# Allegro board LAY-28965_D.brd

Outline 66.22 x 66.22 mm; copper layers: TOP, L2, L3, BOTTOM. Coordinates in mm from the lower left corner of the outline.
Outline path: 0,66.22 66.22,66.22 66.22,0 0,0 0,66.22

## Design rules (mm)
constraint set DEFAULT: min track width 0.2, pair gap 0.2

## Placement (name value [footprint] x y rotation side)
C1  0.47UF  [CC0603_OV]  56.88 27.21 270 bottom
C5  100PF  [CC0603_OV]  42.8 57.2 90 bottom
C6  100PF  [CC0603_OV]  61.33 53.51 270 bottom
C7  0.01uF  [CC0402_25]  56 43.9 180 bottom
C8  0.01uF  [CC0402_25]  57 46.99 180 bottom
C9  0.01uF  [CC0402_25]  60.02 48.39 180 bottom
C10  0.01uF  [CC0402_25]  56.08 36.63 180 bottom
C11  0.01uF  [CC0402_25]  60.02 36.2 0 bottom
C12  0.01uF  [CC0402_25]  60.02 33.43 180 bottom
C13  2200pF  [CC0402_25]  6.67 47.16 270 bottom
C14  15nF  [CC0402_25]  10.38 49.01 0 bottom
C15  470PF  [CC0603_OV]  3.09 47.1 0 bottom
C16  220PF  [CC0603_OV]  33.27 57.2 90 bottom
C17  2200pF  [CC0402_25]  5.73 59.29 180 bottom
C18  15nF  [CC0402_25]  10.81 59.29 0 bottom
C20  0.1uF  [CC0603_OV]  51.79 32.77 90 bottom
C21  2200pF  [CC0402_25]  35.05 56.94 270 bottom
D1  MMBZ27VCLT1  [SOT23_A]  27.44 58.28 180 bottom
D2  MMBZ27VCLT1  [SOT23_A]  21.73 58.65 180 bottom
D3  MMBZ27VCLT1  [SOT23_A]  54.63 58.11 180 bottom
D4  MMBZ27VCLT1  [SOT23_A]  50.68 57.99 90 bottom
D5  MMBZ27VCLT1  [SOT23_A]  60.39 58.11 180 bottom
J1  HDR 1X2  [HDR102]  54.33 26.93 270 top
J2  NP583-016-009  [SKT_QFN16_0P8_25SQ_TH]  34.1 35.75 0 top
J3  HDR 1X2  [HDR102]  51.79 23.88 90 top
J4  HDR 1X2  [HDR102]  55.73 19.05 0 top
J5  HDR 1X2  [HDR102]  52.68 19.05 0 top
J6  HDR 1X2  [HDR102]  49.63 19.05 0 top
J7  HDR 1X2  [HDR102]  13.57 22.28 180 top
J8  HDR 1X2  [HDR102]  16.74 22.28 180 top
J9  CON 2 SKT  [CON_2P_1MM_SM_4P2X3P3]  17.41 52.94 180 top
J10  CON 2 SKT  [CON_2P_1MM_SM_4P2X3P3]  28.93 52.94 180 top
J11  CON 2 SKT  [CON_2P_1MM_SM_4P2X3P3]  56.07 52.94 180 top
J12  CON 2 SKT  [CON_2P_1MM_SM_4P2X3P3]  50.31 52.94 180 top
J13  CON 2 SKT  [CON_2P_1MM_SM_4P2X3P3]  61.83 52.94 180 top
J14  HDR 1X2  [HDR102]  45.97 51.99 180 top
J16  CON 8 SKT  [CON_8P_1MM_SM_10P2X3P3]  22.46 16.27 180 top
J17  CON 8 SKT  [CON_8P_1MM_SM_10P2X3P3]  12.68 35.69 270 top
J19  CON 8 SKT  [CON_8P_1MM_SM_10P2X3P3]  54.51 40.52 90 top
J28  HDR 1X3  [HDR103_A]  32.97 47.04 270 top
J30  HDR 1X3  [HDR103_A]  47.75 31.41 0 top
J33  HDR 1X3  [HDR103_A]  9.87 51.99 180 top
J34  HDR 1X2  [HDR102]  3.5 51.99 180 top
J36  HDR 1X2  [HDR102]  39.62 51.99 180 top
J37  HDR 1X3  [HDR103_A]  42.24 47.04 270 top
J42  HDR 1X3  [HDR103_A]  6.67 51.99 180 top
J45  CON 2 SKT  [CON_2P_1MM_SM_4P2X3P3]  23.17 52.94 180 top
J46  HDR 1X3  [HDR103_A]  56.87 30.1 270 top
J47  HDR 1X3  [HDR103_A]  47.75 40.3 0 top
J48  5103310-3  [HDR_16M_100_TH_RA]  29.31 12.58 270 top
J49  HDR 1X3  [HDR103_A]  13.07 51.99 180 top
J50  HDR 1X2  [HDR102]  33.27 51.99 180 top
J51  HDR 1X2  [HDR102]  42.8 51.99 180 top
J52  HDR 1X2  [HDR102]  36.45 51.99 180 top
J53  CON 2 SKT  [CON_2P_1MM_SM_4P2X3P3]  62.84 24.39 270 top
J54  5103310-1  [HDR_10M_100_TH_RA]  54.08 12.58 270 top
J55  HDR 1X3  [HDR103_A]  23.73 47.04 270 top
JP3  TEST_POINT  [TP_TH_063]  61.19 30.1 0 top
JP4  5124  [TP_TH_063]  44.68 16.64 0 top
JP5  5124  [TP_TH_063]  37.06 16.64 0 top
JP6  5124  [TP_TH_063]  40.87 16.64 0 top
JP9  5124  [TP_TH_063]  33.25 16.64 0 top
JP11  TEST POINT  [TP_TH_063]  7.99 62.14 0 top
JP12  TESTPOINT GREEN  [TP_TH_063]  39.62 60.56 0 top
JP13  TESTPOINT GREEN  [TP_TH_063]  43.43 60.56 0 top
JP14  TESTPOINT GREEN  [TP_TH_063]  58.11 60.56 0 top
JP15  5007  [TP_TH_063]  47.24 60.56 0 top
JP16  5007  [TP_TH_063]  62.51 38.61 0 top
JP17  5124  [TP_TH_063]  62.51 34.8 0 top
JP18  5007  [TP_TH_063]  62.51 42.8 0 top
JP19  5124  [TP_TH_063]  62.51 46.99 0 top
JP20  TEST POINT BLUE  [TP_TH_063]  16.12 62.14 0 top
JP21  5007  [TP_TH_063]  5.44 41.91 0 top
JP22  5007  [TP_TH_063]  5.44 37.59 0 top
JP23  5007  [TP_TH_063]  5.44 33.27 0 top
JP25  5006  [TP_TH_063]  12.06 62.14 0 top
JP26  5007  [TP_TH_063]  5.44 29.46 0 top
JP27  5006  [TP_TH_063]  50.08 43.99 0 top
JP28  5006  [TP_TH_063]  8.31 18.05 0 top
JP29  5006  [TP_TH_063]  15.13 46.7 0 top
JP30  5006  [TP_TH_063]  63.37 10.12 0 top
JP31  TEST_POINT  [TP_TH_063]  46.91 47.23 0 top
JP32  TESTPOINT GREEN  [TP_TH_063]  59.45 19.4 0 top
JP33  TESTPOINT GREEN  [TP_TH_063]  63 15.77 0 top
JP34  TEST POINT BLUE  [TP_TH_063]  52.82 60.57 0 top
MH1  MH_100mil  [C100-100N]  2.54 63.68 0 top
MH2  MH_100mil  [C100-100N]  2.9 2.67 0 top
MH3  MH_100mil  [C100-100N]  63.68 63.68 0 top
MH4  MH_100mil  [C100-100N]  63.68 2.54 0 top
NOREF  -  []  7.03 37.59 0 top
NOREF#2  -  [unnamed#2]  63.36 60.1 0 top
NOREF#3  -  []  64.1 42.8 0 top
NOREF#4  -  []  48.5 47.23 0 top
NOREF#5  -  []  54.41 60.57 0 top
NOREF#6  -  []  32.61 -3.38 0 top
NOREF#7  -  []  43.92 10.04 90 top
NOREF#8  -  []  7.03 41.91 0 top
NOREF#9  -  []  23.9 23.4 90 top
NOREF#10  -  []  21.29 60.05 0 top
NOREF#11  -  []  22.3 21.8 0 top
NOREF#12  -  []  38.65 16.64 0 top
NOREF#13  -  []  9.58 62.14 0 top
NOREF#14  -  []  2.5 6.26 90 top
NOREF#15  -  []  32.61 -3.38 0 top
NOREF#16  -  []  48.83 60.56 0 top
NOREF#17  -  []  41.21 60.56 0 top
NOREF#18  -  []  -380.1 233.02 0 top
NOREF#19  -  []  13.64 62.14 0 top
NOREF#20  -  []  42.59 -3.38 90 top
NOREF#21  -  []  7.03 33.27 0 top
NOREF#22  -  []  64.1 38.61 0 top
NOREF#23  -  []  20.25 19.75 0 top
NOREF#24  -  [unnamed#2]  63.48 6.35 0 top
NOREF#25  -  []  51.54 12.58 0 top
NOREF#26  -  []  -443.6 -259.85 0 top
NOREF#27  -  []  51.67 43.99 0 top
NOREF#28  -  []  64.95 10.12 0 top
NOREF#29  -  []  2.9 2.67 0 top
NOREF#30  -  []  0 66.22 0 top
NOREF#31  -  []  22.3 21.8 90 top
NOREF#32  -  []  61.04 19.4 0 top
NOREF#33  -  []  21.45 23.1 90 top
NOREF#34  -  []  30.55 32 0 top
NOREF#35  -  []  2.9 2.67 0 top
NOREF#36  -  []  -240.18 -122.17 0 top
NOREF#37  -  []  2.9 2.67 0 top
NOREF#38  -  []  64.59 15.77 0 top
NOREF#39  -  []  27.77 -77.15 0 top
NOREF#40  -  []  0 0 90 top
NOREF#41  -  []  34.27 35.69 0 top
NOREF#42  -  []  7.03 29.46 0 top
NOREF#43  -  []  36.25 31.2 90 top
NOREF#44  -  []  29.55 32.4 0 top
NOREF#45  -  []  64.1 46.99 0 top
NOREF#46  -  []  43.92 12.58 0 top
NOREF#47  -  []  45.02 60.56 0 top
NOREF#48  -  []  17.71 62.14 0 top
NOREF#49  -  []  59.7 60.56 0 top
NOREF#50  -  []  0 0 0 top
NOREF#51  -  []  62.78 30.1 0 top
NOREF#52  -  []  28.55 32.8 0 top
NOREF#53  -  [unnamed#2]  2.81 59.9 0 top
NOREF#54  -  []  21.45 28.6 90 top
NOREF#55  -  []  46.27 16.64 0 top
NOREF#56  -  []  35.25 32.8 90 top
NOREF#57  -  []  1.28 9.91 0 top
NOREF#58  -  []  64.1 34.8 0 top
NOREF#59  -  []  -17.22 -67.1 0 top
NOREF#60  -  []  42.46 16.64 0 top
NOREF#61  -  []  0 0 0 top
NOREF#62  -  []  2.9 2.67 90 top
NOREF#63  -  []  16.72 46.7 0 top
NOREF#64  -  []  34.84 16.64 0 top
NOREF#65  -  []  9.9 18.05 0 top
NOREF#66  -  []  2.9 2.67 0 top
NOREF#67  -  [unnamed#2]  63.48 6.35 180 bottom
NOREF#68  -  []  44.64 25.47 180 bottom
NOREF#69  -  []  59.81 1.22 180 bottom
NOREF#70  -  [unnamed#2]  63.36 60.1 180 bottom
NOREF#71  -  []  12.45 26.16 90 bottom
NOREF#72  -  []  31.86 1.27 180 bottom
NOREF#73  -  []  1.28 9.91 90 bottom
NOREF#74  -  []  29.88 37.25 180 bottom
NOREF#75  -  [unnamed#2]  2.81 59.9 180 bottom
Q1  NTR4502PT1G  [SOT23]  58.38 54.28 90 bottom
Q2  NTR4501NT1G  [SOT23-28X44]  19.17 55.5 90 bottom
R1  1K  [RC0402_25]  55.22 21.15 0 top
R2  1K  [RC0402_25]  52.3 21.15 0 top
R3  0  [RC0402_25]  14.07 20.13 180 top
R4  0  [RC0402_25]  17.25 20.13 180 top
R5  1K  [RC0402_25]  49.13 21.15 0 top
R6  100k  [RC0402_25]  55.57 54.47 90 bottom
R9  20K  [RC0402_25]  45.97 56.94 270 bottom
R10  100k  [RC0402_25]  15.27 54.02 270 bottom
R11  20K  [RC0402_25]  16.67 54.02 270 bottom
R15  510  [RC0402_25]  57.58 38.1 270 bottom
R16  510  [RC0402_25]  57.59 35.1 270 bottom
R17  510  [RC0402_25]  60.02 34.8 0 bottom
R18  0  [RC0402_25]  60.02 38.61 180 bottom
R19  510  [RC0402_25]  57.55 43.39 90 bottom
R20  510  [RC0402_25]  58.5 45.52 90 bottom
R21  510  [RC0402_25]  60.02 46.99 0 bottom
R22  0  [RC0402_25]  60.02 42.8 180 bottom
R24  82  [RC0603_OV]  7.43 49.01 0 bottom
R25  27.4  [RC0603_OV]  3.09 49.01 180 bottom
R30  27.4  [RC0603_OV]  8.27 59.29 0 bottom
R31  0  [RC0402_25]  7.93 41.91 180 bottom
R32  0  [RC0402_25]  7.93 37.59 180 bottom
R33  0  [RC0402_25]  7.93 33.27 180 bottom
R34  0  [RC0402_25]  7.93 29.46 180 bottom
R35  330 OHM  [RC0402_25]  36.45 56.94 90 bottom

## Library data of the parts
C1 C5-C18 C20 C21 = CAP_NP
D1-D5 = DZ_DUAL_CK_A1A2C
J1 J3-J8 J14 J34 J36 J50-J52 = CONN_HDR_2X1
J2 = QFNSOCKET16P_4PGND
J9-J13 J45 J53 = CONN_2X1_SH
J16 J17 J19 = CONN_8X1_SH
J28 J30 J33 J37 J42 J46 J47 J49 J55 = CONN_HDR_3X1
J48 = CONN_SHRHDR_8X2
J54 = CONN_HDR_5X2
JP3 JP11-JP14 JP20 JP25 JP27-JP34 = TEST_POINT
JP4-JP6 JP9 JP15-JP19 JP21-JP23 JP26 = T POINT TH
MH1-MH4 = Mounting_Hole_1P
Q1 = MOSFET_P
Q2 = MOSFET_N
R1-R6 R9-R11 R15-R22 R24 R25 R30-R35 = RES

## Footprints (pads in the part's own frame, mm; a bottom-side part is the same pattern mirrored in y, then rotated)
C100-100N
  round 0.254 hole 2.54 unplated: (0,0)
CC0402_25
  round 0.635 smd: 1(-0.508,0) 2(0.508,0)
CC0603_OV
  oval 0.889x1.143 smd: 1(-0.762,0) 2(0.762,0)
CON_2P_1MM_SM_4P2X3P3
  rect 0.61x1.6 smd: 1(-0.5,-1.55) 2(0.5,-1.55)
  rect 1.219x1.803 smd: S1(-1.8,0.95) S2(1.8,0.95)
CON_8P_1MM_SM_10P2X3P3
  rect 0.61x1.6 smd: 1(-3.5,-1.55) 2(-2.5,-1.55) 3(-1.5,-1.55) 4(-0.5,-1.55) 5(0.5,-1.55) 6(1.5,-1.55) 7(2.5,-1.55) 8(3.5,-1.55)
  rect 1.219x1.803 smd: S1(-4.8,0.95) S2(4.8,0.95)
HDR102
  rect 1.524x1.524 hole 1.016: 1(0,0)
  round 1.524 hole 1.016: 2(0,-2.54)
HDR103_A
  rect 1.778x1.778 hole 1.143: 1(0,0)
  round 1.778 hole 1.143: 2(0,-2.54) 3(0,-5.08)
HDR_10M_100_TH_RA
  rect 1.524x1.524 hole 0.889: 1(0,0)
  round 1.524 hole 0.889: 2(2.54,0) 3(0,-2.54) 4(2.54,-2.54) 5(0,-5.08) 6(2.54,-5.08) 7(0,-7.62) 8(2.54,-7.62) 9(0,-10.16) 10(2.54,-10.16)
HDR_16M_100_TH_RA
  rect 1.524x1.524 hole 0.889: 1(0,0)
  round 1.524 hole 0.889: 2(2.54,0) 3(0,-2.54) 4(2.54,-2.54) 5(0,-5.08) 6(2.54,-5.08) 7(0,-7.62) 8(2.54,-7.62) 9(0,-10.16) 10(2.54,-10.16) 11(0,-12.7) 12(2.54,-12.7) 13(0,-15.24) 14(2.54,-15.24) 15(0,-17.78) 16(2.54,-17.78)
RC0402_25
  round 0.635 smd: 1(-0.508,0) 2(0.508,0)
RC0603_OV
  oval 0.889x1.143 smd: 1(-0.762,0) 2(0.762,0)
SKT_QFN16_0P8_25SQ_TH
  round 0.254 hole 1.194 unplated: (-11.8,7.25) (-11.8,-13.95) (9.4,7.25) (9.4,-13.95)
  round 0.254 hole 1.6 unplated: (-10.2,-12.35)
  round 0.254 hole 1.499 unplated: (-1.2,-3.35)
  round 0.254 hole 2.108 unplated: (7.8,5.65)
  rect 0.864x0.864 hole 0.559: 1(0,0)
  round 0.864 hole 0.559: 2(-0.8,1) 3(-1.6,-1) 4(-2.4,0) 5(-4.55,-2.15) 6(-5.55,-2.95) 7(-3.55,-3.75) 8(-4.55,-4.55) 9(-2.4,-6.7) 10(-1.6,-7.7) 11(-0.8,-5.7) 12(0,-6.7) 13(2.15,-4.55) 14(3.15,-3.75) 15(1.15,-2.95) 16(2.15,-2.15) 17(-1.2,0) 18(-4.55,-3.35) 19(-1.2,-6.7) 20(2.15,-3.35)
SOT23
  rect 0.762x1.219 smd: 1(-1.016,-1.092) 2(1.016,-1.092) 3(0,1.092)
SOT23-28X44
  rect 0.711x1.118 smd: 1(-0.965,-1.067) 2(0.965,-1.067) 3(0,1.067)
SOT23_A
  rect 0.787x0.889 smd: 1(-0.94,-1.003) 2(0.94,-1.003) 3(0,1.003)
TP_TH_063
  round 2.311 hole 1.6: 1(0,0)
unnamed#2
  round 1.524 smd: (0,0)

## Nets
BUS_I/VCC: D3.1 J1.2 J3.1 J11.2 J33.2 J36.1 J37.1 J47.3 J48.2 J50.1 J52.1 JP12.1 JP31.1 Q1.2(SOURCE) R6.2
GND: C1.2 C5.2 C6.2 C7.2 C8.2 C9.2 C10.2 C11.2 C12.2 C13.2 C14.2 C15.2 C16.2 C17.2 C18.2 C20.2 C21.2 D1.2 D3.2 D4.2 D5.2 J2.7 J2.17 J2.18 J2.19 J2.20 J7.2 J8.2 J9.1 J9.S1 J9.S2 J10.S1 J10.S2 J11.1 J11.S1 J11.S2 J12.1 J12.S1 J12.S2 J13.1 J13.S1 J13.S2 J16.2 J16.4 J16.6 J16.8 J16.S1 J16.S2(SH2) J17.2 J17.4 J17.6 J17.8 J17.S1 J17.S2(SH2) J19.2 J19.4 J19.5 J19.7 J19.S1 J19.S2(SH2) J30.1 J37.3 J45.1 J45.S1 J45.S2 J48.4 J48.8 J48.10 J48.12 J53.1 J53.S1 J53.S2 J54.2 J54.10(B5) J55.3 JP25.1 JP27.1 JP28.1 JP29.1 JP30.1 JP34.1 Q2.2(SOURCE) R9.1 R10.2 R31.1 R32.1 R33.1 R34.1
VBUF/VCCIO: J1.1 J2.13 J46.2 J48.6 J53.2 J54.4 J54.6 JP3.1 R1.1 R2.1 R5.1
VSSOUT: D2.2 J10.1 JP20.1 Q2.3
BUS_0: D4.1 J2.1 J3.2 J12.2 J51.1 JP13.1
BUSOUT: C6.1 D5.1 J13.2 JP14.1 Q1.3
BUSSW_H: J14.1 J28.3 JP15.1(TP) Q1.1 R6.1
BUSSW_L/TEST0: J2.3 J17.1 J48.11 J49.1 JP21.1(TP) R31.2
BUSSW_L/TEST2: J2.5 J17.5 J49.3 JP23.1(TP) R33.2
IDATA: J34.1 J36.2 J47.1
IO2: J2.2 J28.2
IO14: J2.14 J30.2
IO15: J2.15 J37.2
IO16: J2.16 J47.2
PCM0/ARM0: J2.12 J19.6 J48.13 JP18.1(TP) R22.1
PCM0_OUT: C9.1 J19.8 JP19.1(TP) R21.2
PCM1/ARM1: J19.3 J28.1 J30.3 JP16.1(TP) R18.1
PCM1_OUT: C12.1 J19.1 JP17.1(TP) R17.2
SPI_CLK/IIC_SCL: J2.9(IO9) J4.2 J16.5 J48.3 J54.1 J54.7 JP6.1(TP) JP33.1 R3.1
SPI_DIN: J2.10 J16.3 J48.5 J54.8 JP5.1(TP) R4.1
SPI_DOUT/IIC_SDA: J2.11 J5.2 J16.1 J48.7 J54.3 J54.5 JP4.1(TP) JP32.1
SPI_NCS: J2.8 J6.2 J16.7 J48.1 J54.9 JP9.1(TP)
TEST1: J2.4 J17.3 J55.2 JP22.1(TP) R32.2
TEST3: J2.6 J17.7 J48.9 JP26.1(TP) R34.2
VDPL: D1.1 D2.1 J9.2 J10.2 J42.2 J45.2 JP11.1
N16262320: J49.2 R10.1 R11.1
N16263932: C16.1 J50.2
N16629501: C11.1 R16.2 R17.1
N16629509: C10.1 R15.2 R16.1
N16629513: R15.1 R18.2
N16629717: C7.1 R19.2 R20.1
N16629725: C8.1 R20.2 R21.1
N16629777: R19.1 R22.2
N16685534: C14.1 J33.1 R24.2
N16685548: C13.1 J42.1 R24.1 R25.1
N16686513: C15.1 J34.2 R25.2
N16749782: C17.1 J42.3 R30.1
N16749849: C18.1 J33.3 R30.2
N16830665: J8.1 R4.2
N16830677: J7.1 R3.2
N16834962: C1.1 J46.1
N16835010: C20.1 J46.3
N16854681: C21.1 R35.2
N16859991: J6.1 R5.2
N16860108: J4.1 R1.2
N16860113: J5.1 R2.2
N16862292: C5.1 J51.2
N16864132: J52.2 R35.1
N16864682: J14.2 R9.2
N162622360: Q2.1 R11.2

Pads without a net: D1 3; D2 3; D3 3; D4 3; D5 3; J48 14 15 16; J55 1

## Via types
v1: diameter 0.762, hole 0.406, TOP to BOTTOM, 491 vias

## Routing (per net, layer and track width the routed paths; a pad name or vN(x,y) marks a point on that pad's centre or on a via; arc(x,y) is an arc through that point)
BUS_I/VCC: length 145.5
  TOP w0.2: J11.2 v1(55.57,55.98) ; JP12.1 39.62,58.42 40.63,57.41 40.63,53 J36.1 ; J3.1 J1.2
  L3 w0.2: J1.2 49.87,28.85 49.87,33.1 J47.3 45.41,37.56 45.41,45.73 45.67,45.98 45.67,45.99 JP31.1 43.64,47.23 43.45,47.04 J37.1
  BOTTOM w0.2: J36.1 39.62,51.07 42.24,48.44 J37.1 ; J36.1 J52.1 J50.1 32.94,51.66 15.64,51.66 14.06,53.23 11.17,53.23 J33.2 ; J36.1 41,53.37 46.66,53.37 48.27,54.97 R6.2 ; D3.1 v1(55.57,55.98) R6.2 ; Q1.2 56.46,55.29 56.14,54.97 R6.2 ; J3.1 54.24,21.44 54.24,15.82 55.65,14.41 55.65,8.66 54.21,7.23 33.15,7.23 30.33,10.04 J48.2
GND: length 505
  TOP w0.454: JP30.1 63.37,11.48 ; JP30.1 64.72,10.12 ; JP30.1 63.37,8.76 ; JP30.1 62.01,10.12 ; 13.63,30.08 J17.S2 ; J17.S2 14.73,30.89 ; J17.S2 13.63,31.7 ; J17.S2 12.52,30.89 ; J13.1 62.83,54.49 ; J13.1 62.33,55.49 ; J13.1 62.33,53.49 ; 53.46,51.99 J11.S2 ; J11.S2 54.27,50.89 ; J11.S2 55.08,51.99 ; J11.S2 54.27,53.1 ; 47.75,30.32 J30.1 ; J30.1 46.66,31.41 ; J30.1 47.75,32.5 ; J30.1 48.84,31.41 ; J11.1 57.08,54.49 ; J11.1 56.57,55.49 ; J11.1 56.57,53.49 ; J55.3 18.65,48.13 ; J55.3 17.56,47.04 ; J55.3 18.65,45.95 ; J55.3 19.74,47.04 ; 57.06,43.02 J19.7 55.06,43.02 ; 24.96,18.82 J16.2 24.96,16.81 ; 12.13,36.19 J17.4 10.13,36.19 ; J13.S1 63.63,53.1 ; J13.S1 62.82,51.99 ; J13.S1 64.44,51.99 ; J13.S1 63.63,50.89 ; J45.S1 25.78,51.99 ; J45.S1 24.97,53.1 ; J45.S1 24.16,51.99 ; J45.S1 24.97,50.89 ; 52.46,35.72 J19.S1 ; J19.S1 53.56,34.91 ; J19.S1 53.56,36.53 ; J19.S1 54.66,35.72 ; J7.2 14.53,24.82 ; J7.2 12.6,24.82 ; J7.2 13.57,25.78 ; J7.2 13.57,23.86 ; J9.S1 20.02,51.99 ; J9.S1 19.21,50.89 ; J9.S1 18.4,51.99 ; J9.S1 19.21,53.1 ; JP28.1 9.66,18.05 ; JP28.1 8.31,16.7 ; JP28.1 8.31,19.41 ; JP28.1 6.95,18.05 ; J53.1 61.29,25.39 ; J53.1 60.29,24.89 ; J53.1 62.29,24.89 ; 22.96,16.81 J16.4 22.96,18.82 ; JP29.1 16.49,46.7 ; JP29.1 15.13,45.34 ; JP29.1 15.13,48.06 ; JP29.1 13.78,46.7 ; J19.S2 54.66,45.32 ; J19.S2 53.56,44.51 ; J19.S2 53.56,46.13 ; J19.S2 52.46,45.32 ; 55.06,38.02 J19.2 57.06,38.02 ; 10.13,32.19 J17.8 ; J17.8 11.13,31.68 ; J17.8 12.13,32.19 ; J10.S1 30.73,53.1 ; J10.S1 29.92,51.99 ; J10.S1 30.73,50.89 ; J10.S1 31.54,51.99 ; J9.S2 16.42,51.99 ; J9.S2 15.61,50.89 ; J9.S2 14.8,51.99 ; J9.S2 15.61,53.1 ; J45.S2 22.18,51.99 ; J45.S2 21.37,50.89 ; J45.S2 20.56,51.99 ; J45.S2 21.37,53.1 ; J37.3 38.25,47.04 ; J37.3 37.16,45.95 ; J37.3 36.07,47.04 ; J37.3 37.16,48.13 ; 10.7,62.14 JP25.1 ; JP25.1 12.06,63.5 ; JP25.1 13.41,62.14 ; JP25.1 12.06,60.79 ; J12.S1 52.11,53.1 ; J12.S1 51.3,51.99 ; J12.S1 52.11,50.89 ; J12.S1 52.92,51.99 ; 51.46,60.57 JP34.1 ; JP34.1 54.18,60.57 ; JP34.1 52.82,59.22 ; JP34.1 52.82,61.93 ; 15.78,24.82 J8.2 ; J8.2 17.7,24.82 ; J8.2 16.74,23.86 ; J8.2 16.74,25.78 ; J48.4 27.74,10.04 ; J48.4 25.81,10.04 ; J48.4 26.77,9.08 ; J48.4 26.77,11.01 ; 13.63,39.68 J17.S1 ; J17.S1 13.63,41.3 ; J17.S1 14.73,40.49 ; J17.S1 12.52,40.49 ; 23.67,53.49 J45.1 ; J45.1 23.67,55.49 ; J45.1 24.18,54.49 ; 17.66,14.21 J16.S2 ; J16.S2 18.47,15.32 ; J16.S2 17.66,16.42 ; J16.S2 16.85,15.32 ; J54.10 44.88,10.04 ; J54.10 42.96,10.04 ; J54.10 43.92,9.08 ; J54.10 43.92,11.01 ; 55.06,41.02 J19.5 57.06,41.02 ; 63.79,25.38 J53.S1 ; J53.S1 62.69,26.19 ; J53.S1 63.79,27 ; J53.S1 64.9,26.19 ; 18.42,54.49 J9.1 17.91,55.49 ; 47.7,51.99 J12.S2 ; J12.S2 49.32,51.99 ; J12.S2 48.51,50.89 ; J12.S2 48.51,53.1 ; 62.69,22.59 J53.S2 ; J53.S2 64.9,22.59 ; J53.S2 63.79,23.4 ; J53.S2 63.79,21.78 ; J13.S2 60.03,53.1 ; J13.S2 60.84,51.99 ; J13.S2 60.03,50.89 ; J13.S2 59.22,51.99 ; JP27.1 51.44,43.99 ; JP27.1 48.73,43.99 ; JP27.1 50.08,45.35 ; JP27.1 50.08,42.64 ; 20.73,10.04 J48.8 ; J48.8 21.69,11.01 ; J48.8 22.66,10.04 ; J48.8 21.69,9.08 ; 50.81,53.49 J12.1 ; J12.1 50.81,55.49 ; J12.1 51.32,54.49 ; 57.06,51.99 J11.S1 ; J11.S1 57.87,53.1 ; J11.S1 57.87,50.89 ; J11.S1 58.68,51.99 ; J54.2 54.08,11.01 ; J54.2 54.08,9.08 ; J54.2 55.04,10.04 ; J54.2 53.12,10.04 ; 18.45,17.82 J16.8 18.96,16.81 ; J10.S2 27.13,53.1 ; J10.S2 26.32,51.99 ; J10.S2 27.94,51.99 ; J10.S2 27.13,50.89 ; 27.26,14.21 J16.S1 ; J16.S1 26.45,15.32 ; J16.S1 28.07,15.32 ; J16.S1 27.26,16.42 ; J48.12 17.58,10.04 ; J48.12 16.61,9.08 ; J48.12 15.65,10.04 ; J48.12 16.61,11.01 ; 12.13,38.19 J17.2 10.13,38.19 ; 57.06,40.02 J19.4 55.06,40.02 ; J48.10 19.15,11.01 ; J48.10 20.12,10.04 ; J48.10 18.19,10.04 ; J48.10 19.15,9.08 ; 10.13,34.19 J17.6 12.13,34.19
  TOP w0.508: v1(20.93,16.14) 20.96,16.16 J16.6 ; v1(22.94,16.11) 22.96,16.12 J16.4
  L2 w0.454: J48.12 17.68,10.04 ; J48.12 16.61,8.98 ; J48.12 16.61,11.11 ; J48.12 15.55,10.04 ; JP34.1 52.82,62.03 ; JP34.1 52.82,59.12 ; JP34.1 54.27,60.57 ; JP34.1 51.36,60.57 ; JP28.1 8.31,19.51 ; JP28.1 6.85,18.05 ; JP28.1 8.31,16.6 ; JP28.1 9.76,18.05 ; 25.71,10.04 J48.4 ; J48.4 27.84,10.04 ; J48.4 26.77,11.11 ; J48.4 26.77,8.98 ; 10.6,62.14 JP25.1 ; JP25.1 13.51,62.14 ; JP25.1 12.06,63.6 ; JP25.1 12.06,60.69 ; 13.68,46.7 JP29.1 ; JP29.1 15.13,48.15 ; JP29.1 15.13,45.24 ; JP29.1 16.59,46.7 ; 18.09,10.04 J48.10 ; J48.10 19.15,11.11 ; J48.10 20.22,10.04 ; J48.10 19.15,8.98 ; 16.74,23.76 J8.2 ; J8.2 16.74,25.88 ; J8.2 15.68,24.82 ; J8.2 17.8,24.82 ; J54.10 43.92,11.11 ; J54.10 44.98,10.04 ; J54.10 42.86,10.04 ; J54.10 43.92,8.98 ; J37.3 38.35,47.04 ; J37.3 37.16,45.85 ; J37.3 35.97,47.04 ; J37.3 37.16,48.23 ; 53.02,10.04 J54.2 ; J54.2 54.08,11.11 ; J54.2 55.14,10.04 ; J54.2 54.08,8.98 ; J30.1 48.94,31.41 ; J30.1 46.56,31.41 ; J30.1 47.75,30.22 ; J30.1 47.75,32.6 ; 20.63,10.04 J48.8 ; J48.8 21.69,11.11 ; J48.8 21.69,8.98 ; J48.8 22.76,10.04 ; 50.08,42.54 JP27.1 ; JP27.1 50.08,45.45 ; JP27.1 51.54,43.99 ; JP27.1 48.63,43.99 ; JP30.1 64.82,10.12 ; JP30.1 63.37,11.58 ; JP30.1 63.37,8.67 ; JP30.1 61.91,10.12 ; J55.3 18.65,48.23 ; J55.3 17.46,47.04 ; J55.3 19.84,47.04 ; J55.3 18.65,45.85 ; J7.2 13.57,25.88 ; J7.2 13.57,23.76 ; J7.2 14.63,24.82 ; J7.2 12.5,24.82
  L3 w0.454: J48.10 20.22,10.04 ; J48.10 19.15,8.98 ; J48.10 19.15,11.11 ; J48.10 18.09,10.04 ; JP28.1 8.31,19.51 ; JP28.1 6.85,18.05 ; JP28.1 9.76,18.05 ; JP28.1 8.31,16.6 ; JP27.1 50.08,45.45 ; JP27.1 51.54,43.99 ; JP27.1 48.63,43.99 ; JP27.1 50.08,42.54 ; JP30.1 64.82,10.12 ; JP30.1 63.37,11.58 ; JP30.1 61.91,10.12 ; JP30.1 63.37,8.67 ; 15.68,24.82 J8.2 ; J8.2 16.74,25.88 ; J8.2 16.74,23.76 ; J8.2 17.8,24.82 ; 20.63,10.04 J48.8 ; J48.8 22.76,10.04 ; J48.8 21.69,11.11 ; J48.8 21.69,8.98 ; JP29.1 16.59,46.7 ; JP29.1 15.13,48.15 ; JP29.1 15.13,45.24 ; JP29.1 13.68,46.7 ; JP25.1 12.06,63.6 ; JP25.1 12.06,60.69 ; JP25.1 13.51,62.14 ; JP25.1 10.6,62.14 ; JP34.1 54.27,60.57 ; JP34.1 52.82,62.03 ; JP34.1 51.36,60.57 ; JP34.1 52.82,59.12 ; J30.1 47.75,32.6 ; J30.1 48.94,31.41 ; J30.1 47.75,30.22 ; J30.1 46.56,31.41 ; J54.2 55.14,10.04 ; J54.2 53.02,10.04 ; J54.2 54.08,11.11 ; J54.2 54.08,8.98 ; J37.3 37.16,48.23 ; J37.3 35.97,47.04 ; J37.3 37.16,45.85 ; J37.3 38.35,47.04 ; 12.5,24.82 J7.2 ; J7.2 13.57,25.88 ; J7.2 13.57,23.76 ; J7.2 14.63,24.82 ; J48.4 26.77,11.11 ; J48.4 27.84,10.04 ; J48.4 25.71,10.04 ; J48.4 26.77,8.98 ; J55.3 18.65,48.23 ; J55.3 18.65,45.85 ; J55.3 17.46,47.04 ; J55.3 19.84,47.04 ; 15.55,10.04 J48.12 ; J48.12 17.68,10.04 ; J48.12 16.61,8.98 ; J48.12 16.61,11.11 ; J54.10 44.98,10.04 ; J54.10 43.92,11.11 ; J54.10 43.92,8.98 ; J54.10 42.86,10.04
  BOTTOM w0.454: Q2.2 18.97,56.46 ; Q2.2 18.11,57.12 ; Q2.2 17.25,56.46 ; Q2.2 18.11,55.81 ; JP34.1 54.27,60.57 ; JP34.1 52.82,62.03 ; JP34.1 51.36,60.57 ; JP34.1 52.82,59.12 ; D1.2 26.5,58.02 ; D1.2 26.5,56.53 ; D1.2 27.2,57.28 ; D1.2 25.81,57.28 ; 41.92,57.96 C5.2 ; C5.2 42.8,58.7 ; C5.2 43.67,57.96 ; J30.1 48.94,32.6 ; J30.1 48.94,30.22 ; J30.1 46.56,32.6 ; J30.1 46.56,30.22 ; 13.68,46.7 JP29.1 ; JP29.1 16.59,46.7 ; JP29.1 15.13,45.24 ; JP29.1 15.13,48.15 ; JP25.1 12.06,63.6 ; JP25.1 13.51,62.14 ; JP25.1 10.6,62.14 ; JP25.1 12.06,60.69 ; 12.5,24.82 J7.2 ; J7.2 13.57,25.88 ; J7.2 14.63,24.82 ; J7.2 13.57,23.76 ; J55.3 19.84,47.04 ; J55.3 18.65,45.85 ; J55.3 18.65,48.23 ; C15.2 3.85,47.97 ; C15.2 4.59,47.1 ; C15.2 3.85,46.23 ; 4.61,59.29 C17.2 ; C17.2 5.22,58.67 ; C17.2 5.22,59.91 ; D3.2 54.38,57.11 ; D3.2 53.69,57.85 ; D3.2 53.69,56.36 ; D3.2 53,57.11 ; J54.2 54.08,11.11 ; J54.2 53.02,10.04 ; J54.2 55.14,10.04 ; J54.2 54.08,8.98 ; C8.2 56.49,47.61 ; C8.2 55.87,46.99 ; C8.2 56.49,46.38 ; 20.63,10.04 J48.8 ; J48.8 22.76,10.04 ; J48.8 21.69,11.11 ; J48.8 21.69,8.98 ; 45.35,57.45 R9.1 ; R9.1 45.97,58.07 ; R9.1 46.59,57.45 ; C10.2 55.57,37.25 ; C10.2 55.57,36.01 ; C10.2 54.95,36.63 ; C1.2 57.75,26.44 ; C1.2 56.01,26.44 ; C1.2 56.88,25.7 ; C11.2 61.15,36.2 ; C11.2 60.53,35.58 ; C11.2 60.53,36.82 ; C14.2 11.51,49.01 ; C14.2 10.89,48.4 ; C14.2 10.89,49.63 ; 48.63,43.99 JP27.1 ; JP27.1 50.08,42.54 ; JP27.1 51.54,43.99 ; JP27.1 50.08,45.45 ; JP28.1 8.31,19.51 ; JP28.1 8.31,16.6 ; JP28.1 9.76,18.05 ; JP28.1 6.85,18.05 ; 58.9,48.39 C9.2 ; C9.2 59.51,49.01 ; C9.2 59.51,47.77 ; 59.51,32.81 C12.2 ; C12.2 59.51,34.05 ; C12.2 58.9,33.43 ; J48.12 17.47,10.89 ; J48.12 15.76,9.19 ; J48.12 17.47,9.19 ; J48.12 15.76,10.89 ; D4.2 50.42,58.93 ; D4.2 48.93,58.93 ; D4.2 49.67,59.63 ; D4.2 49.67,58.24 ; JP30.1 64.82,10.12 ; JP30.1 61.91,10.12 ; JP30.1 63.37,11.58 ; JP30.1 63.37,8.67 ; 8.44,41.29 R31.1 ; R31.1 8.44,42.52 ; R31.1 9.05,41.91 ; 54.87,43.9 C7.2 ; C7.2 55.49,44.52 ; C7.2 55.49,43.28 ; 60.46,52.75 C6.2 ; C6.2 61.33,52.01 ; C6.2 62.2,52.75 ; R34.1 9.05,29.46 ; R34.1 8.44,30.08 ; R34.1 8.44,28.84 ; J48.4 27.63,9.19 ; J48.4 27.63,10.89 ; J48.4 25.92,10.89 ; J48.4 25.92,9.19 ; 37.16,45.85 J37.3 ; J37.3 38.35,47.04 ; J37.3 35.97,47.04 ; J37.3 37.16,48.23 ; C16.2 34.14,57.96 ; C16.2 32.4,57.96 ; C16.2 33.27,58.7 ; R32.1 9.05,37.59 ; R32.1 8.44,38.21 ; R32.1 8.44,36.97 ; 18.09,10.04 J48.10 ; J48.10 19.15,8.98 ; J48.10 20.22,10.04 ; J48.10 19.15,11.11 ; 16.74,23.76 J8.2 ; J8.2 17.8,24.82 ; J8.2 16.74,25.88 ; J8.2 15.68,24.82 ; D5.2 60.14,57.11 ; D5.2 58.76,57.11 ; D5.2 59.45,57.85 ; D5.2 59.45,56.36 ; R33.1 9.05,33.27 ; R33.1 8.44,32.65 ; R33.1 8.44,33.89 ; 6.67,46.03 C13.2 ; C13.2 6.05,46.65 ; C13.2 7.29,46.65 ; C18.2 11.94,59.29 ; C18.2 11.32,59.91 ; C18.2 11.32,58.67 ; R10.2 15.89,53.52 ; R10.2 15.27,52.9 ; R10.2 14.66,53.52 ; 42.86,10.04 J54.10 ; J54.10 43.92,8.98 ; J54.10 44.98,10.04 ; J54.10 43.92,11.11 ; C20.2 52.66,33.53 ; C20.2 51.79,34.28 ; C20.2 50.92,33.53 ; C21.2 35.67,56.44 ; C21.2 35.05,55.82 ; C21.2 34.43,56.44
  vias: v1(1.08,61.56) v1(1.06,58.78) v1(1.08,56.48) v1(1.08,53.94) v1(1.08,51.4) v1(1.08,48.86) v1(1.08,46.32) v1(1.08,43.78) v1(1.08,41.24) v1(1.08,38.7) v1(1.08,36.16) v1(1.08,33.62) v1(1.08,31.08) v1(1.08,28.54) v1(1.08,26) v1(1.08,23.46) v1(1.08,20.92) v1(1.08,18.38) v1(1.08,15.84) v1(1.08,13.3) v1(1.08,10.76) v1(1.08,8.22) v1(1.08,5.68) v1(3.03,50.36) v1(3.05,41.03) v1(3.05,38.49) v1(3.05,35.95) v1(3.05,33.41) v1(3.05,30.87) v1(3.05,28.33) v1(3.05,25.79) v1(3.05,23.25) v1(3.05,20.71) v1(3.05,18.17) v1(3.05,15.63) v1(3.05,13.09) v1(3.05,10.55) v1(3.05,8.01) v1(3.05,5.47) v1(3.62,43.78) v1(4.34,57.25) v1(4.52,45.76) v1(5.14,50.25) v1(5.18,48.27) v1(5.29,65.11) v1(5.33,63.54) v1(5.38,31.42) v1(5.59,61.03) v1(5.55,27.57) v1(5.59,25.79) v1(5.59,23.25) v1(5.59,20.71) v1(5.59,18.17) v1(5.59,15.63) v1(5.59,13.09) v1(5.59,10.55) v1(5.59,8.01) v1(5.59,5.47) v1(5.59,2.93) v1(5.68,35.77) v1(6.21,39.85) v1(7.51,45.78) v1(7.51,43.24) v1(7.98,65.11) v1(8.13,28.33) v1(8.13,25.79) v1(8.13,23.25) v1(8.13,20.71) v1(8.13,15.63) v1(8.13,13.09) v1(8.13,10.55) v1(8.13,8.01) v1(8.13,5.47) v1(8.13,2.93) v1(8.23,56.69) v1(8.28,54.65) v1(8.4,50.38) v1(8.51,40.28) v1(8.71,36.14) v1(9.07,32.07) v1(10.16,45.65) v1(10.16,43.11) v1(10.29,60.56) v1(10.52,65.11) v1(10.56,63.54) v1(10.57,30.7) v1(10.67,28.33) v1(10.67,25.79) v1(10.67,23.25) v1(10.67,20.71) v1(10.67,18.17) v1(10.67,15.63) v1(10.67,8.01) v1(10.67,5.47) v1(10.67,2.93) v1(11.45,56.74) v1(12.25,45.72) v1(12.25,43.18) v1(12.26,50.44) v1(12.27,48.51) v1(12.55,38.2) v1(12.61,36.31) v1(12.66,59.34) v1(12.81,34.06) v1(12.87,32.35) v1(13,29.05) v1(13.06,65.11) v1(13.1,63.54) v1(13.07,26.56) v1(13.21,15.63) v1(13.21,8.01) v1(13.21,5.47) v1(13.21,2.93) v1(13.59,19.1) v1(14.63,57.62) v1(14.62,48.65) v1(14.67,43.39) v1(14.67,38.31) v1(14.68,36.29) v1(14.8,59.34) v1(14.99,34.21) v1(14.98,32.31) v1(14.98,29.77) v1(14.98,27.23) v1(15.17,56.61) v1(15.46,40.47) v1(15.6,65.11) v1(15.71,50.5) v1(15.75,18.17) v1(15.75,8.01) v1(15.75,5.47) v1(15.75,2.93) v1(16.34,16.17) v1(16.82,57.57) v1(17.23,59.25) v1(17.21,43.39) v1(17.21,40.85) v1(17.21,38.31) v1(17.22,36.29) v1(17.53,34.21) v1(17.52,32.31) v1(17.52,29.77) v1(17.52,27.23) v1(17.6,48.59) v1(17.76,18.18) v1(18.14,65.11) v1(18.14,62.57) v1(18.29,8.01) v1(18.29,5.47) v1(18.29,2.93) v1(18.95,16.02) v1(19.12,13.98) v1(19.27,57.62) v1(19.31,23.82) v1(19.31,21.28) v1(19.36,53.93) v1(19.77,44.1) v1(19.77,41.56) v1(19.77,39.02) v1(20.12,34.96) v1(20.26,36.83) v1(20.3,33.2) v1(20.37,59.44) v1(20.44,31.37) v1(20.44,28.83) v1(20.44,26.29) v1(20.79,50.5) v1(20.84,48.56) v1(20.83,8.01) v1(20.83,5.47) v1(20.83,2.93) v1(21.24,65.15) v1(21.24,62.61) v1(21.41,54.3) v1(23.13,52.6) v1(23.09,34.98) v1(23.23,36.85) v1(23.33,50.5) v1(23.27,33.22) v1(23.38,48.56) v1(23.41,31.39) v1(23.41,28.85) v1(23.41,26.31) v1(23.37,8.01) v1(23.37,5.47) v1(23.37,2.93) v1(23.78,62.61) v1(23.78,60.07) v1(24.56,57.27) v1(24.75,16.14) v1(25.64,34.94) v1(25.61,19.28) v1(25.61,14.27) v1(25.82,33.18) v1(25.87,50.5) v1(25.91,8.01) v1(25.91,5.47) v1(25.91,2.93) v1(25.96,31.35) v1(25.96,28.81) v1(25.96,26.27) v1(26.32,62.61) v1(26.32,60.07) v1(27.05,44.48) v1(27.05,41.94) v1(27.05,39.4) v1(27.05,36.86) v1(28.1,31.35) v1(28.06,21.77) v1(28.08,19.4) v1(28.25,28.85) v1(28.25,26.31) v1(28.41,50.5) v1(28.46,48.56) v1(28.45,8.01) v1(28.45,5.47) v1(28.45,2.93) v1(28.82,52.53) v1(28.86,62.61) v1(28.86,60.07) v1(29.35,44.44) v1(29.35,41.9) v1(29.35,39.36) v1(29.35,36.82) v1(30.57,28.4) v1(30.57,25.86) v1(30.57,23.32) v1(30.62,21.28) v1(30.95,50.5) v1(31,48.56) v1(30.99,10.55) v1(30.99,8.01) v1(30.99,5.47) v1(30.99,2.93) v1(31.09,33.77) v1(31.17,56.09) v1(31.23,31.09) v1(31.24,13.46) v1(31.4,62.61) v1(31.4,60.07) v1(31.82,44.61) v1(31.82,42.07) v1(31.82,39.53) v1(31.82,36.99) v1(31.94,52.68) v1(33.49,50.5) v1(33.54,48.56) v1(33.49,25.86) v1(33.49,23.32) v1(33.53,10.55) v1(33.53,8.01) v1(33.53,5.47) v1(33.53,2.93) v1(33.64,13.74) v1(33.94,62.61) v1(33.94,60.07) v1(34.19,21.17) v1(34.95,55.04) v1(35.11,31.27) v1(35.92,28.34) v1(36.03,50.5) v1(36.03,43.64) v1(36.03,41.1) v1(36.03,38.56) v1(36.03,36.02) v1(36.03,25.86) v1(36.03,23.32) v1(36.07,10.55) v1(36.07,8.01) v1(36.07,5.47) v1(36.07,2.93) v1(36.18,13.74) v1(36.29,21.19) v1(36.48,62.61) v1(36.48,60.07) v1(36.54,48.49) v1(38.02,55.75) v1(38.57,50.5) v1(38.62,48.56) v1(38.57,43.64) v1(38.57,41.1) v1(38.57,38.56) v1(38.57,36.02) v1(38.57,33.48) v1(38.57,30.94) v1(38.57,28.4) v1(38.57,25.86) v1(38.57,23.32) v1(38.61,10.55) v1(38.61,8.01) v1(38.61,5.47) v1(38.61,2.93) v1(38.69,21.3) v1(38.72,13.74) v1(38.89,65.19) v1(38.89,62.65) v1(40.87,18.84) v1(41.11,50.5) v1(41.11,38.56) v1(41.11,36.02) v1(41.11,33.48) v1(41.11,30.94) v1(41.11,28.4) v1(41.11,25.86) v1(41.16,48.56) v1(41.15,10.55) v1(41.15,8.01) v1(41.15,5.47) v1(41.15,2.93) v1(41.43,65.19) v1(41.43,62.65) v1(41.59,55.3) v1(41.72,13.72) v1(42.78,15.19) v1(43.49,50.5) v1(43.7,48.56) v1(43.67,45.72) v1(43.65,38.56) v1(43.65,36.02) v1(43.65,33.48) v1(43.65,30.94) v1(43.65,28.4) v1(43.65,25.86) v1(43.69,8.01) v1(43.69,5.47) v1(43.69,2.93) v1(43.97,65.19) v1(43.97,62.65) v1(43.98,18.69) v1(44.82,14.93) v1(44.88,55.9) v1(45.75,48.64) v1(45.68,35.95) v1(46.19,50.5) v1(46.19,43.64) v1(46.19,41.1) v1(46.19,38.56) v1(46.19,33.48) v1(46.19,30.94) v1(46.19,28.4) v1(46.19,25.86) v1(46.23,8.01) v1(46.23,5.47) v1(46.23,2.93) v1(46.28,45.42) v1(46.51,65.19) v1(46.51,62.65) v1(46.98,14.31) v1(47.09,23.81) v1(47.13,18.85) v1(47.22,21.23) v1(47.37,17) v1(48.27,55.75) v1(48.73,50.5) v1(48.78,48.56) v1(48.77,8.01) v1(48.77,5.47) v1(48.77,2.93) v1(48.93,46.8) v1(49.05,65.19) v1(49.05,62.65) v1(49.05,60.11) v1(49.32,27.25) v1(49.69,40.03) v1(50.1,51.73) v1(50.22,24.39) v1(51.27,41.1) v1(51.27,38.56) v1(51.31,8.01) v1(51.31,5.47) v1(51.31,2.93) v1(51.4,59.07) v1(51.36,36.07) v1(51.59,65.19) v1(51.59,62.65) v1(51.58,50.25) v1(51.73,48.5) v1(51.91,44.67) v1(52.09,54.14) v1(52.12,22.38) v1(52.26,56.85) v1(52.64,46.54) v1(53.15,34.2) v1(53.15,32.16) v1(53.47,58.89) v1(53.81,50.5) v1(53.81,43.64) v1(53.81,41.1) v1(53.83,38.16) v1(53.86,48.56) v1(53.85,8.01) v1(53.85,5.47) v1(53.85,2.93) v1(54.13,65.19) v1(54.13,62.65) v1(54.44,54.12) v1(55.04,32.14) v1(55.08,34.23) v1(56.03,51.88) v1(56.34,35.58) v1(56.36,60.13) v1(56.35,50.5) v1(56.4,48.56) v1(56.39,23.25) v1(56.39,13.09) v1(56.39,10.55) v1(56.39,8.01) v1(56.39,5.47) v1(56.39,2.93) v1(56.49,45.46) v1(56.67,65.19) v1(56.67,62.65) v1(56.95,24.77) v1(57.1,32.15) v1(57.74,57.05) v1(58.03,40.49) v1(58.22,54.29) v1(58.27,48.77) v1(58.29,33.45) v1(58.66,37.5) v1(58.89,50.5) v1(58.93,30.87) v1(58.93,28.33) v1(58.93,25.79) v1(58.93,23.25) v1(58.93,15.63) v1(58.93,13.09) v1(58.93,10.55) v1(58.93,8.01) v1(58.93,5.47) v1(58.93,2.93) v1(59.21,65.19) v1(59.21,62.65) v1(59.16,40.63) v1(59.49,43.73) v1(59.56,45.95) v1(61.02,37.74) v1(61.42,51.15) v1(61.37,22.88) v1(61.5,40.63) v1(61.47,33.41) v1(61.47,28.33) v1(61.47,20.71) v1(61.47,18.17) v1(61.47,13.09) v1(61.47,8.01) v1(61.47,5.47) v1(61.47,2.93) v1(61.57,61.14) v1(61.62,48.64) v1(61.75,65.19) v1(61.75,62.65) v1(61.77,25.9) v1(63.93,24.32) v1(64.01,56.27) v1(64.01,53.73) v1(64.01,48.65) v1(64.01,46.11) v1(64.01,41.03) v1(64.01,35.95) v1(64.01,33.41) v1(64.01,30.87) v1(64.01,28.33) v1(64.01,20.71) v1(64.01,18.17) v1(64.01,13.09) v1(64.12,43.66) v1(64.38,38.42) v1(64.99,8.15) v1(65.14,61.84) v1(65.09,4.46) v1(65.2,65.16)
VBUF/VCCIO: length 97
  TOP w0.2: J48.6 24.23,8.69 25.8,7.12 46.89,7.12 49,9.22 J54.6 J54.4 52.69,11.19 52.69,14.59 54.14,16.04 54.14,20.58 R1.1 ; R1.1 54.14,21.72 52.36,21.72 51.79,21.15 51.22,21.72 49.19,21.72 R5.1 ; R1.1 54.71,21.93 55.43,22.65 55.43,25.83 J1.1 J46.2 55.74,31.51 59.78,31.51 JP3.1 59.6,28.51 59.6,24.38 60.09,23.89 J53.2
  BOTTOM w0.2: J2.13 37.08,31.2 40.55,27.73 48.61,27.73 49.58,28.69 52.92,28.69 J46.2
VSSOUT: length 19.9
  TOP w0.2: J10.1 29.43,55.89 v1(29.43,55.89)
  BOTTOM w0.2: JP20.1 16.12,62.14 18.7,59.56 18.87,59.56 D2.2 20.24,57.09 Q2.3 20.37,55.5 20.6,55.26 28.8,55.26 v1(29.43,55.89)
BUS_0: length 71.9
  TOP w0.2: JP13.1 43.43,58.26 44.06,57.63 44.06,53.25 J51.1 42.8,51.08 41.2,49.49 35.71,49.49 34.9,48.68 34.9,41.7 34.1,40.9 J2.1 ; J12.2 v1(49.81,55.98)
  L3 w0.2: v1(49.81,55.98) 47.14,53.3 44.11,53.3 J51.1
  BOTTOM w0.2: v1(49.81,55.98) 49.81,56.92 D4.1 ; J3.2 53.03,25.19 49.98,25.19 49.49,24.7 40.64,24.7 34.22,31.13 34.22,33.98 34.1,34.1 J2.1
BUSOUT: length 12.1
  TOP w0.2: J13.2 v1(61.33,55.98) 61.33,57.34 JP14.1
  BOTTOM w0.2: Q1.3 C6.1 v1(61.33,55.98) D5.1
BUSSW_H: length 41.7
  TOP w0.2: J14.1 47.24,53.26 JP15.1
  L3 w0.2: J14.1 43.49,49.51 30.36,49.51 J28.3
  BOTTOM w0.2: J14.1 48.84,51.99 49.59,52.75 54.36,52.75 R6.1 56.27,53.26 Q1.1
BUSSW_L/TEST0: length 80.3
  TOP w0.2: v1(11.13,40.18) J17.1 8.15,39.19 JP21.1
  BOTTOM w0.2: J2.3 27.81,34.75 17.07,45.48 17.07,47.99 J49.1 13.07,42.13 v1(11.13,40.18) 11.13,32.21 11.5,31.84 11.5,19.92 16.61,14.8 J48.11 ; R31.2 JP21.1
BUSSW_L/TEST2: length 50.6
  TOP w0.2: JP23.1 7.36,35.19 11.13,35.19 ; 11.13,35.19 J17.5 ; 11.13,35.19 v1(12.74,35.19) 18.27,35.19 19.26,34.19 28.95,34.19 J2.5
  L3 w0.2: v1(12.74,35.19) 11.92,36.01 11.92,41.94 11.49,42.36 11.49,55.49 J49.3
  BOTTOM w0.2: R33.2 JP23.1
IDATA: length 70.3
  L3 w0.2: J36.2 42.45,57.36 49.93,57.36 50.85,56.45 50.85,47.71 47.75,44.62 J47.1
  BOTTOM w0.2: J36.2 38.42,53.33 20.94,53.33 19,55.27 14.57,55.27 14.09,55.76 5.67,55.76 5.01,55.09 5.01,53.5 J34.1
IO2: length 11.5
  TOP w0.2: J28.2 30.43,42.19 33.3,39.31 33.3,36.75 J2.2
IO14: length 11.8
  TOP w0.2: J2.14 38.75,32 41.14,29.61 47.01,29.61 J30.2
IO15: length 16.1
  TOP w0.2: J37.2 37.62,44.95 37.62,41.55 35.25,39.19 J2.15
IO16: length 13.2
  TOP w0.2: J2.16 37.42,33.6 41.58,37.76 J47.2
PCM0/ARM0: length 72.8
  TOP w0.2: J2.12 35.53,27.62 48.49,27.62 49.59,28.72 49.59,38.19 53.42,42.02 J19.6 57.25,42.02 57.41,41.86 59.84,41.86 60.78,42.8 JP18.1
  BOTTOM w0.2: J2.12 34.1,27.56 30.98,24.43 28.28,24.43 18.01,14.15 18.01,12.23 17.16,11.39 15.27,11.39 J48.13 ; R22.1 JP18.1
PCM0_OUT: length 11.1
  TOP w0.2: JP19.1 60.5,44.99 57.55,44.99 56.58,44.02 J19.8
  BOTTOM w0.2: C9.1 R21.2 JP19.1
PCM1/ARM1: length 58.7
  TOP w0.2: J30.3 49.6,26.33 50.34,27.07 50.34,36.15 53.21,39.02 J19.3 57.68,39.02 57.91,39.24 60.04,39.24 60.67,38.61 JP16.1
  BOTTOM w0.2: JP16.1 R18.1 59.59,39.55 51.62,39.55 46.45,44.71 35.3,44.71 J28.1
PCM1_OUT: length 10.9
  TOP w0.2: J19.1 56.64,37.02 56.87,36.78 56.87,36.43 57.43,35.87 59.31,35.87 60.38,34.8 JP17.1
  BOTTOM w0.2: C12.1 R17.2 JP17.1
SPI_CLK/IIC_SCL: length 91.7
  TOP w0.2: J54.1 54.08,14.86 J4.2 59.97,16.51 60.71,15.77 JP33.1 ; J48.3 25.76,11.57 23.82,11.57 22.94,12.44 22.94,14.54 21.96,15.52 J16.5 21.96,18.72 21.72,18.96 15.76,18.96 R3.1 ; J2.9 31.7,20.96 35.15,17.51 35.15,15.77 36.12,14.8 39.03,14.8 JP6.1 40.87,12.97 42.27,11.57 45.45,11.57 J54.7
  BOTTOM w0.2: J48.3 26.77,15.55 30.43,19.21 38.31,19.21 JP6.1 ; J54.7 47.86,13.98 52.56,13.98 53.96,12.58 J54.1
SPI_DIN: length 58.6
  TOP w0.2: J2.10 32.5,21.2 JP5.1 ; J48.5 24.23,14.27 23.96,14.54 J16.3 23.96,18.8 23.45,19.31 18.58,19.31 R4.1
  BOTTOM w0.2: J54.8 45.19,11.32 45.19,13.39 44.02,14.56 39.14,14.56 JP5.1 35.3,18.4 31.06,18.4 27.87,15.21 27.87,12.02 27.22,11.38 25.44,11.38 J48.5
SPI_DOUT/IIC_SDA: length 77.4
  TOP w0.2: J5.2 51.54,15.37 J54.3 J54.5 ; J16.1 v1(25.96,16.27)
  L3 w0.2: JP32.1 57.85,17.8 53.97,17.8 J5.2 ; J2.11 32.89,30.46 32.18,30.46 32.08,30.36 31,30.36 29.19,28.55 29.19,24.15 21.69,16.65 J48.7
  BOTTOM w0.2: J48.7 23.98,14.87 24.55,14.87 v1(25.96,16.27) 29.75,20.07 41.25,20.07 JP4.1 46.31,15.02 51.19,15.02 J5.2
SPI_NCS: length 59.5
  TOP w0.2: JP9.1 29.55,20.34 J2.8 ; J16.7 19.96,14.14 20.42,13.67 20.42,12.04 20.94,11.52 23.19,11.52 23.56,11.15 25.84,11.15 26.21,11.52 28.25,11.52 J48.1 ; J54.9 47.85,16.51 J6.2
  BOTTOM w0.2: J54.9 J48.1 31.42,14.69 31.42,14.81 JP9.1
TEST1: length 47.2
  TOP w0.2: JP22.1 8.9,37.59 9.29,37.19 J17.3 18.33,37.19 19.77,35.75 J2.4 28.3,39.15 28.3,44.33 27.16,45.47 22.75,45.47 J55.2
  BOTTOM w0.2: R32.2 JP22.1
TEST3: length 50.6
  TOP w0.2: J2.6 28.06,32.3 18.68,32.3 17.79,33.19 11.13,33.19 ; 11.13,33.19 J17.7 ; 11.13,33.19 9.17,33.19 JP26.1 9.54,25.35 9.54,20.71 16.66,13.6 18.14,13.6 J48.9
  BOTTOM w0.2: R34.2 JP26.1
VDPL: length 39.8
  TOP w0.2: JP11.1 5.22,59.37 5.22,55.91 6.6,54.53 J42.2 7.83,53.37 14.15,53.37 15.27,54.49 J9.2 16.91,55.46 17.72,56.26 22.31,56.26 v1(22.67,55.9) ; v1(22.67,55.9) 23.03,56.26 28.06,56.26 v1(28.43,55.89) J10.2 ; v1(22.67,55.9) J45.2
  BOTTOM w0.2: v1(28.43,55.89) 28.38,55.94 D1.1 ; D2.1 v1(22.67,55.9)
N16262320: length 3.6
  BOTTOM w0.2: J49.2 R10.1 R11.1
N16263932: length 1.9
  BOTTOM w0.2: C16.1 J50.2
N16629501: length 3.4
  BOTTOM w0.2: R16.2 57.96,34.59 58.12,34.75 58.49,34.75 v1(58.54,34.8) R17.1 C11.1
N16629509: length 3
  BOTTOM w0.2: C10.1 v1(57.58,36.63) ; v1(57.58,36.63) 57.58,35.61 R16.1 ; v1(57.58,36.63) R15.2
N16629513: length 1.9
  BOTTOM w0.2: R15.1 v1(58.55,38.61) R18.2
N16629717: length 3
  BOTTOM w0.2: R20.1 v1(58.5,44.05) 58.42,43.97 57.62,43.97 R19.2 C7.1
N16629725: length 3
  BOTTOM w0.2: v1(58.5,46.99) R21.1 ; v1(58.5,46.99) R20.2 ; v1(58.5,46.99) C8.1
N16629777: length 2
  BOTTOM w0.2: R22.2 v1(58.5,42.8) 57.63,42.8 R19.1
N16685534: length 4.7
  BOTTOM w0.2: J33.1 C14.1 R24.2
N16685548: length 7.1
  BOTTOM w0.2: R24.1 3.86,49.01 R25.1 ; R24.1 C13.1 ; R24.1 J42.1
N16686513: length 7.9
  BOTTOM w0.2: J34.2 2.33,53.36 R25.2 C15.1
N16749782: length 3.8
  BOTTOM w0.2: J42.3 7.51,57.91 R30.1 C17.1
N16749849: length 3.8
  BOTTOM w0.2: C18.1 R30.2 9.03,57.91 J33.3
N16830665: length 2.1
  TOP w0.2: R4.2 J8.1
N16830677: length 2.1
  TOP w0.2: R3.2 J7.1
N16834962: length 2.1
  BOTTOM w0.2: C1.1 56.87,27.98 J46.1
N16835010: length 1.9
  BOTTOM w0.2: C20.1 J46.3
N16854681: length 2
  BOTTOM w0.2: R35.2 35.75,58.14 v1(35.75,58.16) C21.1
N16859991: length 2.1
  TOP w0.2: R5.2 J6.1
N16860108: length 2.1
  TOP w0.2: R1.2 J4.1
N16860113: length 2.1
  TOP w0.2: J5.1 52.68,20.34 52.81,20.47 R2.2
N16862292: length 1.9
  BOTTOM w0.2: C5.1 J51.2
N16864132: length 1.9
  BOTTOM w0.2: R35.1 J52.2
N16864682: length 1.9
  BOTTOM w0.2: R9.2 J14.2
N162622360: length 3.1
  BOTTOM w0.2: Q2.1 18.11,53.88 18.14,53.84 18.14,53.45 v1(17.54,52.85) 17.19,53.2 16.99,53.2 R11.2

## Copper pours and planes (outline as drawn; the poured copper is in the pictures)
GND on TOP: 65.59,0.64 0.64,0.64 0.64,65.59 65.59,65.59 ; 35 cut-outs
GND on BOTTOM: 0.64,0.64 0.64,65.59 65.59,65.59 65.59,0.64 ; 4 cut-outs
GND on L2: 0.64,0.64 0.64,65.59 65.59,65.59 65.59,0.64
GND on L3: 0.64,0.64 0.64,65.59 65.59,65.59 65.59,0.64

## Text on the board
BOTTOM: 170-28965 REV D | 8 OF 11 | SECONDARY SIDE
Board Geometry/Soldermask Bottom: 9 OF 11 | SECONDARY SOLDERMASK
Ref Des/Silkscreen Bottom: 10 OF 11 | SECONDARY SILKSCREEN
User.Comments: 1 OF 1 | TEST PROBE
TOP: 5 OF 11 | PRIMARY SIDE
Board Geometry/Soldermask Top: 4 OF 11 | PRIMARY SOLDERMASK
Ref Des/Silkscreen Top: ARM0 | OUT | ARM1 | SEN-GEN6-SKT | 2 OF 11 | PRIMARY SILKSCREEN
L2: 6 OF 11 | EARTH GROUND PLANE
L3: 7 OF 11 | GROUND PLANE
PASTEMASK_TOP: 1 OF 11 | PRIMARY SOLDER PASTE
XSECTION_CHART: L2 CONDUCTOR - COPPER 0.689 MIL | *  DIELECTRIC - FR-4-IMPOSE 8 MIL | L3 CONDUCTOR - COPPER 0.689 MIL | L4 BOTTOM CONDUCTOR - COPPER 0.472 MIL | *  SURFACE - AIR 0 MIL | L1 TOP CONDUCTOR - COPPER 0.472 MIL | *  DIELECTRIC - FR-4-IMPOSE 2.48 MIL | DESIGN CROSS SECTION CHART | ___________________________ | TOTAL THICKNESS 20.803 MIL | 1-4
DIMENSION: SECONDARY DATUM | SKT J2 PIN 1 | PRIMARY DATUM | GRID ORIGIN | SEE DETAIL C | VIEW FROM PRIMARY SIDE
PASTEMASK_BOTTOM: SECONDARY SOLDER PASTE | 11 OF 11
User.7: SCALE: NONE | 1 | 11. ELECTRICAL TEST - 100% IPCD356. PCB FABRICATOR TO PERFORM A NET COMPARE AGAINST THE IPCD356 NETLIST PROVIDED BY NXP. | 16 | 17 | 8 | DETAIL C
User.13: 3 OF 11 | PRIMARY SILKSCREEN2
User.21: THIS DOCUMENT CONTAINS INFORMATION | PROPRIETARY TO NXP AND SHALL NOT | BE USED FOR ENGINEERING DESIGN | PROCUREMENT OR MANUFACTURE IN WHOLE | OR IN PART WITHOUT THE CONSENT OF | NXP. | ___ COMPANY PUBLIC | ___ COMPANY INTERNAL | ___ COMPANY CONFIDENTIAL | X | NXP SEMICONDUCTORS
User.45: ALL PARTS, MATERIALS AND FINISHED | ASSEMBLY SHALL NOT CONTAIN ANY OF | THE SUBSTANCES OF VERY HIGH CONCERN | (SVHC) ABOVE THE THRESHOLD VALUE PER | THE CURRENT ECHA LIST OF SVHC'S AND | WITH ANNEX XIV AND ANNEX XVII OF REACH | DIRECTIVE 76/769/EEC. A CERTIFICATE OF | COMPLIANCE IS REQUIRED UPON REQUEST. | ASSEMBLY SHALL MEET THE RoHS | COMMISSION DELEGATED DIRECTIVE (EU) | 2015/863 OF 31 MARCH  2015 AMENDING | ANNEX II TO DIRECTIVE 2011/65/EU. A | CERTIFICATE OF COMPLIANCE IS | REQUIRED UPON REQUEST. | ___ PUBI (PUBLIC INFORMATION) | ___ IUO (NXP INTERNAL USE ONLY) | ___ CP (NXP CONFIDENTIAL PROPRIETARY) | THIS DOCUMENT CONTAINS INFORMATION | PROPRIETARY TO NXP AND SHALL NOT | BE USED FOR ENGINEERING DESIGN | PROCUREMENT OR MANUFACTURE IN WHOLE | OR IN PART WITHOUT THE CONSENT OF | NXP. | X | ANTHONY DUHAMEL | 09-17-20 | 11-08-19 | 05-17-16 | D.A. | R.B. | A.M. | B | C | D | Re-SPIN Per ECO113683 | ECOXXXXXX ADDED J55 | Re-SPIN Per ECO64811 | FIGURE | FINISHED_SIZE | 16.0 | 22.0 | 35.0 | 40.0 | 45.0 | 63.0 | 47.0 | 59.0 | 83.0 | 100.0 | DRILL CHART: TOP to BOTTOM | ALL UNITS ARE IN MILS | TOLERANCE_DRILL | +2.0/-16.0 | +2.0/-2.0 | +3.0/-3.0 | +4.0/-2.0 | PLATED | NON-PLATED | QTY | 491 | 20 | 26 | 27 | 28 | 4 | 1 | NXP SEMICONDUCTORS
